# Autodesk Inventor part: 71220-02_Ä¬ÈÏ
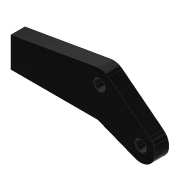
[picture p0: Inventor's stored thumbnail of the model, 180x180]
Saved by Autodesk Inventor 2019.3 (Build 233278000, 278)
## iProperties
Created: 2010-06
Part Number: 71220-02_Ä¬ÈÏ
Material: Ogólny
Document SubType Name: Modeling
Designer: CADENGINEERING4
Density: 1 g/cm^3
Appearance: Gładki — czarny
Author: CADENGINEERING4
Revision Number: ÈÎºÎ
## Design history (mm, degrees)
feature "NONE"
node "Bryła1"
